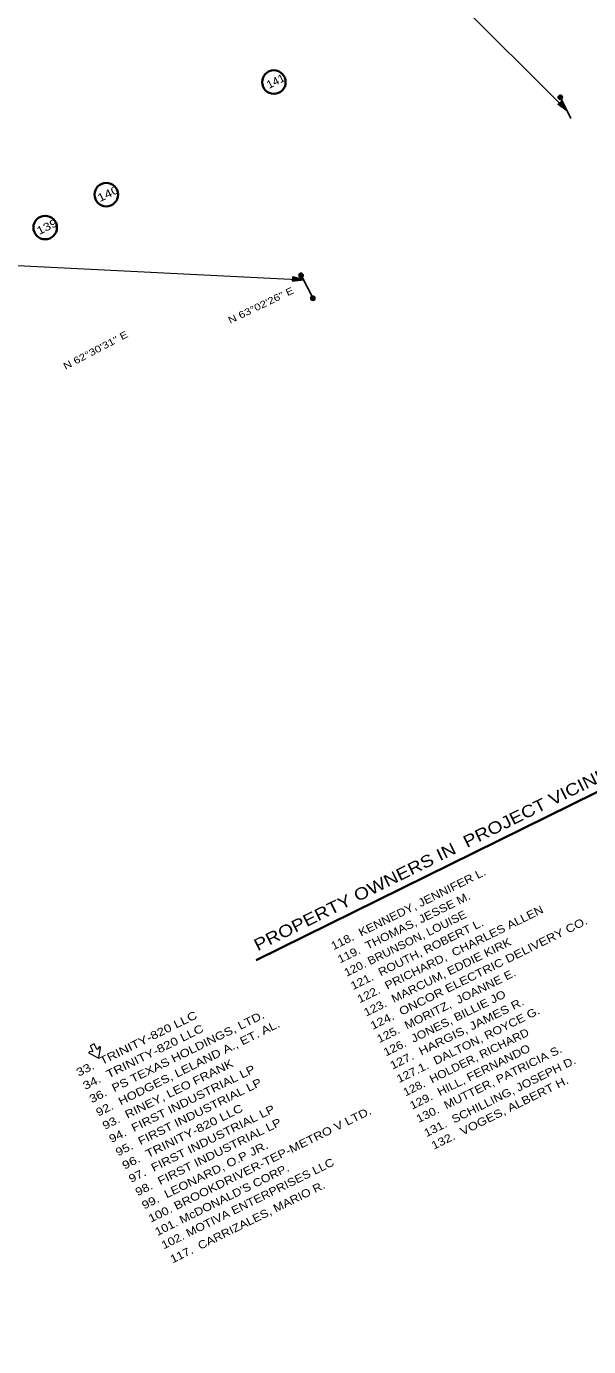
# Model space of a CAD drawing. Extents: x 2356431 to 2371438, y 6972864 to 6982525.
# Drawn here: x 2360481 to 2361464, y 6975322 to 6977631 of the extents above; entities that cross this region are included whole.
import ezdxf
from ezdxf.enums import TextEntityAlignment as Align

# ---------------------------------------------------------------- set-up
doc = ezdxf.new("R2010")
doc.units = 0
doc.header["$LTSCALE"] = 5.6
for name, color, linetype, lineweight in [('17', 7, 'Continuous', 35), ('18', 7, 'Continuous', 35), ('28', 7, 'Continuous', 35), ('48', 7, 'Continuous', 25), ('53', 7, 'Continuous', 13)]:
    doc.layers.add(name, color=color, linetype=linetype, lineweight=lineweight)

msp = doc.modelspace()

# ---------------------------------------------------------------- hatches: boundary and pattern name
at = {"layer": '48'}
for points in [[(2361426.415, 6977483.624), (2361415.946, 6977500.118), (2361410.685, 6977495.202)], [(2361418.361, 6977507.236, 1), (2361410.898, 6977507.321, 1)], [(2360964.982, 6977195.873, 1), (2360957.519, 6977195.958, 1)], [(2360965.928, 6977188.142), (2360946.983, 6977192.91), (2360946.55, 6977185.716)], [(2360985.593, 6977155.703, 1), (2360978.13, 6977155.788, 1)]]:
    msp.add_hatch(color=256, dxfattribs=at).paths.add_polyline_path(points)

# ---------------------------------------------------------------- linework, layer by layer
at = {"layer": '17'}
for centre in [(2360913.684, 6977533.818), (2360620.591, 6977337.031), (2360513.73, 6977279.374)]:
    msp.add_circle(centre, 20.576, dxfattribs=at)
at = {"layer": '18'}
msp.add_line((2360882.78, 6975997.85), (2361530.348, 6976317.447), dxfattribs=at)
at = {"layer": '48', "lineweight": 13}
for p, q in [((2360950.551, 6977959.272), (2361426.415, 6977483.624)), ((2359930.257, 6977239.372), (2360965.928, 6977188.142))]:
    msp.add_line(p, q, dxfattribs=at)
at = {"layer": '48'}
for p, q in [((2361414.934, 6977506.696), (2361432.978, 6977470.111)), ((2360961.796, 6977195.02), (2360982.203, 6977155.299))]:
    msp.add_line(p, q, dxfattribs=at)
for points in [[(2361426.415, 6977483.624), (2361415.946, 6977500.118), (2361410.685, 6977495.202)], [(2360965.928, 6977188.142), (2360946.983, 6977192.91), (2360946.55, 6977185.716)]]:
    msp.add_lwpolyline(points, close=True, dxfattribs=at)
for centre in [(2361414.63, 6977507.278), (2360961.25, 6977195.915), (2360981.862, 6977155.745)]:
    msp.add_circle(centre, 3.732, dxfattribs=at)
at = {"layer": '53'}
for p, q in [((2360596.663, 6975838.023), (2360591.151, 6975837.41)), ((2360603.978, 6975842.32), (2360603.956, 6975842.329)), ((2360608.891, 6975846.166), (2360605.064, 6975842.166))]:
    msp.add_line(p, q, dxfattribs=at)
for points in [[(2360590.821, 6975835.494), (2360607.646, 6975826.311), (2360610.613, 6975845.254)], [(2360603.956, 6975842.329), (2360599.366, 6975851.652), (2360595.971, 6975849.972), (2360592.593, 6975848.308), (2360597.184, 6975838.992)]]:
    msp.add_lwpolyline(points, dxfattribs=at)
for centre, radius, start, end in [((2360591.282, 6975836.402), 1.012, 96.13904, 241.52017), ((2360596.593, 6975838.677), 0.675, 276.27556, 26.25867), ((2360604.584, 6975842.619), 0.675, 206.25867, 316.24177), ((2360609.621, 6975845.449), 1.012, 350.99716, 136.3783)]:
    msp.add_arc(centre, radius, start, end, dxfattribs=at)
at = {"layer": '53', "lineweight": 35}
msp.add_spline([(2361346.062, 6975144.535), (2361358.396, 6975151.177), (2361370.685, 6975157.911), (2361382.928, 6975164.736), (2361395.125, 6975171.656), (2361407.277, 6975178.667), (2361419.384, 6975185.77), (2361431.444, 6975192.967), (2361443.458, 6975200.255), (2361455.428, 6975207.636), (2361467.351, 6975215.109), (2361479.228, 6975222.676), (2361491.061, 6975230.335), (2361502.847, 6975238.086), (2361514.588, 6975245.929), (2361526.283, 6975253.866), (2361537.932, 6975261.894), (2361549.536, 6975270.015), (2361561.093, 6975278.229), (2361572.606, 6975286.535), (2361584.072, 6975294.934), (2361595.493, 6975303.425), (2361606.869, 6975312.008), (2361618.198, 6975320.685), (2361629.482, 6975329.453), (2361640.721, 6975338.314), (2361651.913, 6975347.268), (2361663.06, 6975356.314), (2361674.161, 6975365.453), (2361685.216, 6975374.684), (2361696.226, 6975384.008), (2361707.191, 6975393.423), (2361718.109, 6975402.932), (2361728.982, 6975412.534), (2361739.809, 6975422.227), (2361750.591, 6975432.013), (2361761.326, 6975441.892), (2361772.017, 6975451.863), (2361782.661, 6975461.926), (2361793.26, 6975472.082), (2361803.813, 6975482.331), (2361814.321, 6975492.672), (2361824.782, 6975503.105), (2361835.199, 6975513.631), (2361845.569, 6975524.25), (2361855.894, 6975534.961), (2361866.173, 6975545.764), (2361876.406, 6975556.661), (2361886.594, 6975567.649), (2361896.736, 6975578.731), (2361906.832, 6975589.904)], degree=3, dxfattribs=at)

# ---------------------------------------------------------------- texts
at = {"layer": '17'}
for s, width, p in [('141', 1.05, (2360919.879, 6977529.069)), ('140', 1.25, (2360626.786, 6977332.282)), ('139', 1.2, (2360519.925, 6977274.625))]:
    msp.add_text(s, height=14, rotation=26.268, dxfattribs=dict(at, width=width)).set_placement(p, align=Align.CENTER)
at = {"layer": '18'}
for s, height, width, p in [('PROPERTY OWNERS IN  PROJECT VICINITY', 21, 1.2, (2360885.329, 6976013.393)), ('118.  KENNEDY, JENNIFER L.', 14, 1.15, (2361017.848, 6976015.264)), ('119.  THOMAS, JESSE M. ', 14, 1.15, (2361029.311, 6975992.037)), ('120. BRUNSON, LOUISE', 14, 1.1, (2361040.774, 6975968.811)), ('122.  PRICHARD,  CHARLES ALLEN', 14, 1.15, (2361063.7, 6975922.358)), ('121.  ROUTH, ROBERT L.', 14, 1.15, (2361052.237, 6975945.584)), ('124.  ONCOR ELECTRIC DELIVERY CO.', 14, 1.2, (2361086.626, 6975875.904)), ('123.  MARCUM, EDDIE KIRK', 14, 1.15, (2361075.163, 6975899.131)), ('125.  MORITZ,  JOANNE E.', 14, 1.15, (2361098.09, 6975852.678)), ('126.  JONES, BILLIE JO', 14, 1.15, (2361109.552, 6975829.451)), ('127.  HARGIS, JAMES R. ', 14, 1.2, (2361121.015, 6975806.226)), ('33.  TRINITY-820 LLC', 14, 1.25, (2360572.308, 6975794.053)), ('36.  PS TEXAS HOLDINGS, LTD.', 14, 1.2, (2360595.234, 6975747.6)), ('127.1.  DALTON, ROYCE G.', 14, 1.15, (2361132.589, 6975782.774)), ('34.  TRINITY-820 LLC', 14, 1.25, (2360583.771, 6975770.827)), ('92.  HODGES, LELAND A., ET. AL.', 14, 1.2, (2360606.697, 6975724.374)), ('128.  HOLDER, RICHARD', 14, 1.1, (2361144.053, 6975759.548)), ('129.  HILL, FERNANDO', 14, 1.15, (2361155.516, 6975736.321)), ('130.  MUTTER, PATRICIA S.', 14, 1.15, (2361166.978, 6975713.094)), ('93.  RINEY, LEO FRANK', 14, 1.2, (2360618.16, 6975701.147)), ('94.  FIRST INDUSTRIAL LP', 14, 1.2, (2360629.623, 6975677.921)), ('131.  SCHILLING, JOSEPH D. ', 14, 1.15, (2361180.571, 6975688.31)), ('95.  FIRST INDUSTRIAL LP', 14, 1.2, (2360641.086, 6975654.694)), ('132.  VOGES, ALBERT H.', 14, 1.2, (2361193.266, 6975666.15)), ('96.  TRINITY-820 LLC', 14, 1.25, (2360652.549, 6975631.467)), ('97.  FIRST INDUSTRIAL LP', 14, 1.2, (2360664.013, 6975608.241)), ('98.  FIRST INDUSTRIAL LP', 14, 1.2, (2360675.475, 6975585.014)), ('100. BROOKDRIVER-TEP-METRO V LTD.', 14, 1.2, (2360698.402, 6975538.562)), ('99.  LEONARD, O.P JR.', 14, 1.2, (2360686.938, 6975561.789)), ('102. MOTIVA ENTERPRISES LLC', 14, 1.15, (2360721.327, 6975492.108)), ("101. McDONALD'S CORP.", 14, 1.15, (2360709.865, 6975515.335)), ('117.  CARRIZALES, MARIO R. ', 14, 1.15, (2360736.654, 6975467.395))]:
    msp.add_text(s, height=height, rotation=26.268, dxfattribs=dict(at, width=width)).set_placement(p)
at = {"layer": '28', "width": 1.25}
for s, rotation, p in [('N 63°02\'26" E', 25.784, (2360893.541, 6977137.954)), ('N 62°30\'31" E', 27.784, (2360604.559, 6977059.458))]:
    msp.add_text(s, height=12, rotation=rotation, dxfattribs=at).set_placement(p, align=Align.CENTER)

doc.saveas('drawing.dxf')
